// Mitsubishi GX Works2 project: Weight 1 - LK-E4HW   PLC: FX3U/FX3UC

PROGRAM MAIN
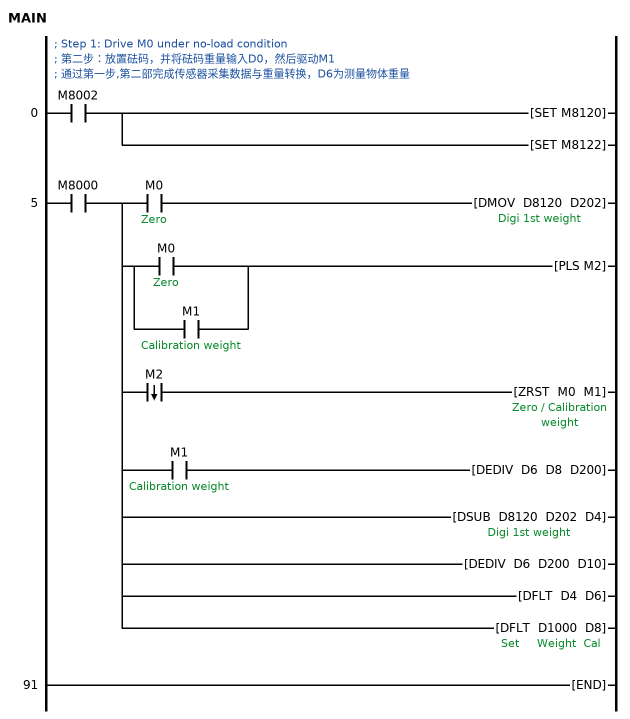
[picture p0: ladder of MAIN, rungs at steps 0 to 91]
; Step 1: Drive M0 under no-load condition
; 第二步：放置砝码，并将砝码重量输入D0，然后驱动M1
; 通过第一步,第二部完成传感器采集数据与重量转换，D6为测量物体重量
0     LD      M8002
      SET     M8120
      SET     M8122
5     LD      M8000
      MPS
      AND     M0  ; Zero
      DMOV    D8120 D202  ; Digi 1st weight
      MRD
      LD      M0  ; Zero
      OR      M1  ; Calibration weight
      ANB
      PLS     M2
      MRD
      ANDF    M2
      ZRST    M0 M1
      MRD
      AND     M1  ; Calibration weight
      DEDIV   D6 D8 D200
      MPP
      DSUB    D8120 D202 D4
      DEDIV   D6 D200 D10
      DFLT    D4 D6
      DFLT    D1000 D8  ; Set     Weight  Cal
91    END
END_PROGRAM

// device comments not shown above
D0  ; weight  Cal
D2  ; display weight
D100  ; Digi 1st weight
D102  ; Digi 2nd weight
D104  ; Digi 3rd weight
D106  ; Digi 4th weight
D108  ; Digi 5th weight
D110  ; Digi 6th weight
D1048  ; Digi 3rd weight
D1050  ; Digi 4th weight
D1052  ; Digi 5th weight
D1054  ; Digi 6th weight
